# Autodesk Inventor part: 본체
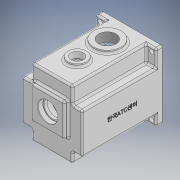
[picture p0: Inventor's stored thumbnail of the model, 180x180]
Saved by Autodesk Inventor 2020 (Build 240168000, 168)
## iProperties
Created: 2022-01
Part Number: 본체
Material: 일반
Document SubType Name: Modeling
Designer: user
Density: 1 g/cm^3
Appearance: 기본값
Mass: 521.293 g
Surface Area: 1157.23 cm^2
Volume: 521.293 cm^3
Author: user
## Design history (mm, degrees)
sketch "스케치1"
  geometry: L1 (49, -55)-(-49, -55); L2 (-49, -55)-(-49, 55); L3 (-49, 55)-(49, 55); L4 (49, 55)-(49, -55); L5 (49, -55)-(-49, 55); L6 (-49, -55)-(49, 55); 1 further point
  constraints: 12 end point, 2 midpoint, 2 parallel, 1 horizontal, 1 perpendicular
  dimensions: "d0" = 98 distance of L2.end L3.end; "d1" = 110 distance of L1.end L2.end
extrude "돌출1" new body sketch "스케치1" distance "d2" = 130; taper "d3" = 0 deg
sketch "스케치2"
  geometry: L1 (-49, 55)-(-49, -55) reference; L2 (-49, -55)-(-33, -55); L3 (-33, -55)-(-33, -38); L4 (-33, -38)-(-49, -38); L5 (-49, -38)-(-49, -55); L6 (49, 55)-(-49, 55) reference; L7 (-49, 55)-(-33, 55); L8 (-33, 55)-(-33, 28); L9 (-33, 28)-(-49, 28); L10 (-49, 28)-(-49, 55); L11 (0, 55)-(0, -55); L12 (-49, -55)-(49, -55) reference; L13 (49, 55)-(33, 55); L14 (33, 55)-(33, 28); L15 (33, 28)-(49, 28); L16 (49, 28)-(49, 55); L17 (49, -55)-(33, -55); L18 (33, -55)-(33, -38); L19 (33, -38)-(49, -38); L20 (49, -38)-(49, -55); 5 further points
  constraints: 34 end point, 6 symmetric about line, 4 parallel, 2 horizontal, 2 midpoint, 2 perpendicular
  dimensions: "d4" = 16 distance of L3.end L4.end; "d5" = 17 distance of L2.end L3.end; "d6" = 16 distance of L8.end L9.end; "d7" = 27 distance of L7.end L8.end
extrude "돌출2" cut sketch "스케치2" distance "d8" = 120; taper "d9" = 0 deg
sketch "스케치3"
  geometry: L1 (49, 0)-(49, -130); L2 (82, -130)-(16, -130) reference; L3 (98, 0)-(0, 0) reference; C1 r 15 at (49, -89); C2 r 22.5 at (49, -40)
  constraints: 2 centre point, 2 end point, 2 point on line, 1 midpoint
  dimensions: "d10" = 30 diameter of C1; "d11" = 45 diameter of C2; "d12" = 40 distance from line of L3 C2.centre; "d13" = 49 distance of C1.centre C2.centre
extrude "돌출3" join sketch "스케치3" distance "d14" = 5; taper "d15" = 0 deg
sketch "스케치4"
  geometry: L1 (22.5, 60)-(-22.5, 60) reference; L2 (0, 60)-(0, -55); L3 (33, -55)-(-33, -55) reference; L4 (49, -55)-(-49, -55) reference; L5 (23, -1)-(-23, -1); L6 (-23, -1)-(-23, 30.143); L7 (-23, 45)-(23, 45); L8 (23, 45)-(23, 30.143); L9 (23, -1)-(-23, 45); L10 (-23, -1)-(23, 45); L11 (-23, 30.143)-(-23, 45); L12 (23, 30.143)-(23, -1); A1 r 42 centre (0, -5) between (23, 30.143) and (-23, 30.143); A2 r 42 centre (0, -5) between (0, -47) and (23, 30.143); A3 r 42 centre (0, -5) between (-23, 30.143) and (0, -47); 2 further points
  constraints: 18 end point, 6 point on circle, 5 parallel, 4 midpoint, 3 centre point, 3 point on line, 2 perpendicular, 1 horizontal
  dimensions: "d35" = 84 diameter of A1; "d36" = 50 distance from line of L4 A1.centre; "d37" = 46 distance of L7.start L7.end; "d38" = 46 distance of L5.end L7.start; "d39" = 50 distance from line of A1.centre L7
extrude "돌출4" cut sketch "스케치4" distance "d20" = 121; taper "d21" = 0 deg
sketch "스케치7"
  geometry: L1 (33, 55)-(-33, 55) reference; L2 (0, 55)-(0, -55); L3 (-33, -55)-(33, -55) reference; L4 (27, -21)-(-27, -21); L5 (-27, -21)-(-27, 33); L6 (-27, 33)-(27, 33); L7 (27, 33)-(27, -21); L8 (27, -21)-(-27, 33); L9 (-27, -21)-(27, 33); A1 r 42 centre (0, -5) between (-23, 30.143) and (23, 30.143) reference; 2 further points
  constraints: 14 end point, 4 midpoint, 2 parallel, 1 horizontal, 1 perpendicular, 1 point on line
  dimensions: "d40" = 54 distance of L5.end L6.end; "d41" = 54 distance of L4.end L5.end; "d42" = 11 distance of point (0, 6) A1.centre
extrude "돌출7" join sketch "스케치7" distance "d43" = 7; taper "d44" = 0 deg
fillet "모깎기3" dims "d45" = 6
fillet "모깎기4" dims "d46" = 3
sketch "스케치8"
  geometry: L1 (23, 42)-(23, 33.249) reference; L2 (-20, 45)-(20, 45) reference; L3 (-23, 33.249)-(-23, 42) reference; L4 (-26, 33.249)-(-26, 42); L5 (-20, 48)-(20, 48); L6 (26, 42)-(26, 33.249); A1 r 42 centre (0, -5) between (-25.375, 28.468) and (25.375, 28.468) reference; A2 r 6 centre (29, 33.249) between (23, 33.249) and (25.375, 28.468) reference; A3 r 3 centre (20, 42) between (23, 42) and (20, 45) reference; A4 r 3 centre (-20, 42) between (-20, 45) and (-23, 42) reference; A5 r 6 centre (-29, 33.249) between (-25.375, 28.468) and (-23, 33.249) reference; A6 r 45 centre (0, -5) between (-27.188, 30.859) and (27.187, 30.859); A7 r 3 centre (-29, 33.249) between (-27.188, 30.859) and (-26, 33.249); A8 r 6 centre (-20, 42) between (-20, 48) and (-26, 42); A9 r 6 centre (20, 42) between (26, 42) and (20, 48); A10 r 3 centre (29, 33.249) between (26, 33.249) and (27.187, 30.859); 1 further point
  constraints: 10 point on circle, 6 end point, 5 centre point, 7 other
  dimensions: "d47" = 3 radial gap between concentric circles of A1 A6
extrude "돌출8" cut sketch "스케치8" distance "d48" = 9; taper "d49" = 0 deg
chamfer "모따기2" distance "d50" = 1; stored, may be unused: second distance "d51" = 2, angle "d52" = 45 deg
sketch "스케치9"
  geometry: C1 r 15 at (20, -32) reference; C2 r 22.5 at (20, -81) reference; C3 r 15 at (20, -32); 1 further point
  constraints: 1 centre point, 1 coincident
  dimensions: "d53" = 30 diameter of C3
extrude "돌출9" cut sketch "스케치9" distance "d54" = 5; taper "d55" = 0 deg
sketch "스케치10"
  geometry: C1 r 15 at (0, 0) reference; 2 further points
  constraints: 1 coincident
hole "구멍1" sketch "스케치10" at (0, 0) diameter "d56" = 20; stored, may be unused: countersink angle "d60" = 90 deg, drill point angle "d62" = 0 deg; dims "d57" = 4, "d58" = 4, "d59" = 2, "d61" = 6
chamfer "모따기3" distance "d63" = 1; stored, may be unused: second distance "d64" = 2, angle "d65" = 45 deg
sketch "스케치11"
  geometry: C1 r 22.5 at (0, 0) reference; 2 further points
  constraints: 1 coincident
hole "구멍2" sketch "스케치11" at (0, 0) diameter "d66" = 28.376; stored, may be unused: countersink angle "d70" = 90 deg, drill point angle "d72" = 0 deg; dims "d67" = 60, "d68" = 4, "d69" = 2, "d71" = 67.3
sketch "스케치12"
  geometry: L1 (27, 33)-(-27, 33) reference; L2 (27, -21)-(27, 33) reference; L3 (-27, 33)-(27, 33) reference; L4 (0, 33)-(0, -21); L5 (-27, 33)-(-27, -21) reference; L6 (-27, -21)-(27, -21) reference; L7 (-27, -21)-(-27, 33) reference; L8 (-27, 6)-(27, 6); L9 (27, 33)-(27, -21) reference; C1 r 16 at (0, 6); A1 r 42 centre (0, -5) between (-25.375, 28.468) and (25.375, 28.468) reference; 1 further point
  constraints: 4 end point, 4 midpoint, 1 centre point, 1 vertical
  dimensions: "d73" = 32 diameter of C1
extrude "돌출10" cut sketch "스케치12" distance "d74" = 8.3; taper "d75" = 0 deg
sketch "스케치13"
  geometry: C1 r 16 at (0, 6) reference; C2 r 21 at (0, 6); 1 further point
  constraints: 1 centre point, 1 coincident
  dimensions: "d76" = 42 diameter of C2
extrude "돌출11" join sketch "스케치13" distance "d77" = 7; taper "d78" = 0 deg
sketch "스케치14"
  geometry: C1 r 21 at (0, 0) reference; C2 r 16 at (0, 0); 1 further point
  constraints: 1 centre point, 1 coincident
  dimensions: "d79" = 32 diameter of C2
extrude "돌출12" cut sketch "스케치14" distance "d80" = 10; taper "d81" = 0 deg
sketch "스케치15"
  geometry: C1 r 16 at (0, 0) reference; C2 r 14 at (0, 0); 1 further point
  constraints: 1 centre point, 1 coincident
  dimensions: "d82" = 28 diameter of C2
extrude "돌출13" cut sketch "스케치15" stored distance "d83" = 10; taper "d84" = 0 deg
sketch "스케치16"
  geometry: L1 (33, -55)-(-33, -55) reference; L2 (0, -55)-(0, 55); L3 (-33, 55)-(33, 55) reference; C1 r 15 at (0, -25); 1 further point
  constraints: 2 end point, 2 midpoint, 1 centre point, 1 point on line
  dimensions: "d85" = 30 diameter of C1; "d86" = 30 distance from line of L1 C1.centre
extrude "돌출14" join sketch "스케치16" distance "d87" = 7; taper "d88" = 0 deg
sketch "스케치17"
  geometry: C1 r 11 at (0, -25); A1 r 15 centre (0, -25) between (-8.978, -12.984) and (8.978, -12.984) reference; 1 further point
  constraints: 1 centre point, 1 coincident
  dimensions: "d89" = 22 diameter of C1
extrude "돌출15" cut sketch "스케치17" distance "d90" = 7; taper "d91" = 0 deg
sketch "스케치18"
  geometry: C1 r 11 at (0, 0) reference; C2 r 9.5 at (0, 0); 1 further point
  constraints: 1 centre point, 1 coincident
  dimensions: "d92" = 19 diameter of C2
extrude "돌출16" cut sketch "스케치18" distance "d93" = 3; taper "d94" = 0 deg
fillet "모깎기5" dims "d95" = 3
fillet "모깎기6" dims "d96" = 0.3
chamfer "모따기4" distance "d97" = 1; stored, may be unused: second distance "d98" = 2, angle "d99" = 45 deg
chamfer "모따기5" distance "d100" = 0.8; stored, may be unused: second distance "d101" = 2, angle "d102" = 30 deg
fillet "모깎기7" dims "d103" = 0.3
fillet "모깎기8" dims "d104" = 3
fillet "모깎기9" dims "d105" = 3
fillet "모깎기10" dims "d106" = 3
chamfer "모따기6" distance "d107" = 1; stored, may be unused: second distance "d108" = 2, angle "d109" = 30 deg
sketch "스케치19"
  geometry: L1 (0, -5)-(-36, -5); L2 (0, -5)-(36, -5); L3 (-36, -5)-(-36, -1); L4 (-36, -1)-(-41.809, -1); L5 (-36, -1)-(-36, -9); L6 (-36, -9)-(-41.809, -9); L7 (36, -1)-(36, -9); L8 (36, -1)-(41.809, -1); L9 (36, -9)-(41.809, -9); A1 r 42 centre (0, -5) between (-25.375, 28.468) and (25.375, 28.468) reference; A2 r 36 centre (0, -5) between (-36, -5) and (36, -5); A3 r 4 centre (-36, -5) between (-36, -9) and (-36, -1); A4 r 4 centre (36, -5) between (36, -1) and (36, -9); A5 r 42 centre (0, -5) between (-25.375, 28.468) and (25.375, 28.468) reference; A6 r 4 centre (36, -5) between (36, -9) and (36, -1); A7 r 4 centre (-36, -5) between (-36, -1) and (-36, -9); 4 further points
  constraints: 18 end point, 14 point on circle, 5 centre point, 5 horizontal, 3 coincident, 3 tangent, 2 vertical, 1 parallel
  dimensions: "d110" = 72 diameter of A2; "d111" = 8 diameter of A3; "d112" = 8 diameter of A4
extrude "돌출17" join sketch "스케치19" stored distance "d113" = 3; taper "d114" = 0 deg
fillet "모깎기11" dims "d115" = 3
sketch "스케치20"
  geometry: A1 r 4 centre (-36, -5) between (-36, -9) and (-36, -1) reference; A2 r 4 centre (36, -5) between (36, -1) and (36, -9) reference; 3 further points
  constraints: 2 coincident
hole "구멍3" sketch "스케치20" at (-36, -5), (36, -5) diameter "d116" = 3.242; stored, may be unused: countersink angle "d120" = 90 deg, drill point angle "d122" = 118 deg; dims "d117" = 7, "d118" = 4, "d119" = 2, "d121" = 9
fillet "모깎기12" dims "d123" = 3
fillet "모깎기13" dims "d124" = 3
fillet "모깎기14" dims "d125" = 3
fillet "모깎기15" dims "d126" = 3
fillet "모깎기16" dims "d127" = 3
fillet "모깎기17" dims "d128" = 3
sketch "스케치21"
  geometry: L1 (-130, 77)-(-130, 17) reference; L2 (-7, 107)-(-127, 107) reference; 2 further points
  constraints: 1 other
  dimensions: "d129" = 65 distance from line of L1 point (-65, 47); "d130" = 60 distance from line of L2 point (-65, 47)
feature "엠보싱1" sketch "스케치21" dims "d131" = 0.5, "d132" = 0
sketch "스케치22"
  geometry: L1 (-46, 55)-(46, 55) reference; L2 (-49, -52)-(-49, 52) reference; L3 (46, -55)-(-46, -55) reference; L4 (49, 52)-(49, -52) reference; L5 (0, 55)-(0, -55); L6 (30, -55)-(-30, -55) reference; 5 further points
  constraints: 2 end point, 2 midpoint, 2 symmetric about line
  dimensions: "d133" = 7 distance from line of point (-42, 48) L1; "d134" = 7 distance from line of L2 point (-42, 48); "d135" = 7 distance from line of point (-42, -48) L3; "d136" = 7 distance from line of point (-42, -48) L2
hole "구멍4" sketch "스케치22" at (-42, 48), (-42, -48), (42, 48), (42, -48) diameter "d137" = 7; stored, may be unused: countersink angle "d141" = 90 deg, drill point angle "d143" = 0 deg; dims "d138" = 7, "d139" = 4, "d140" = 2, "d142" = 10
fillet "모깎기18" dims "d144" = 3
node "솔리드1"
feature "A9D066F2-1C7D-4E18-AEED-F7BC21143FA4" dims "d137" = 7, "d138" = 7, "d139" = 4, "d140" = 2, "d141" = 90 deg, "d142" = 10, "d143" = 0
